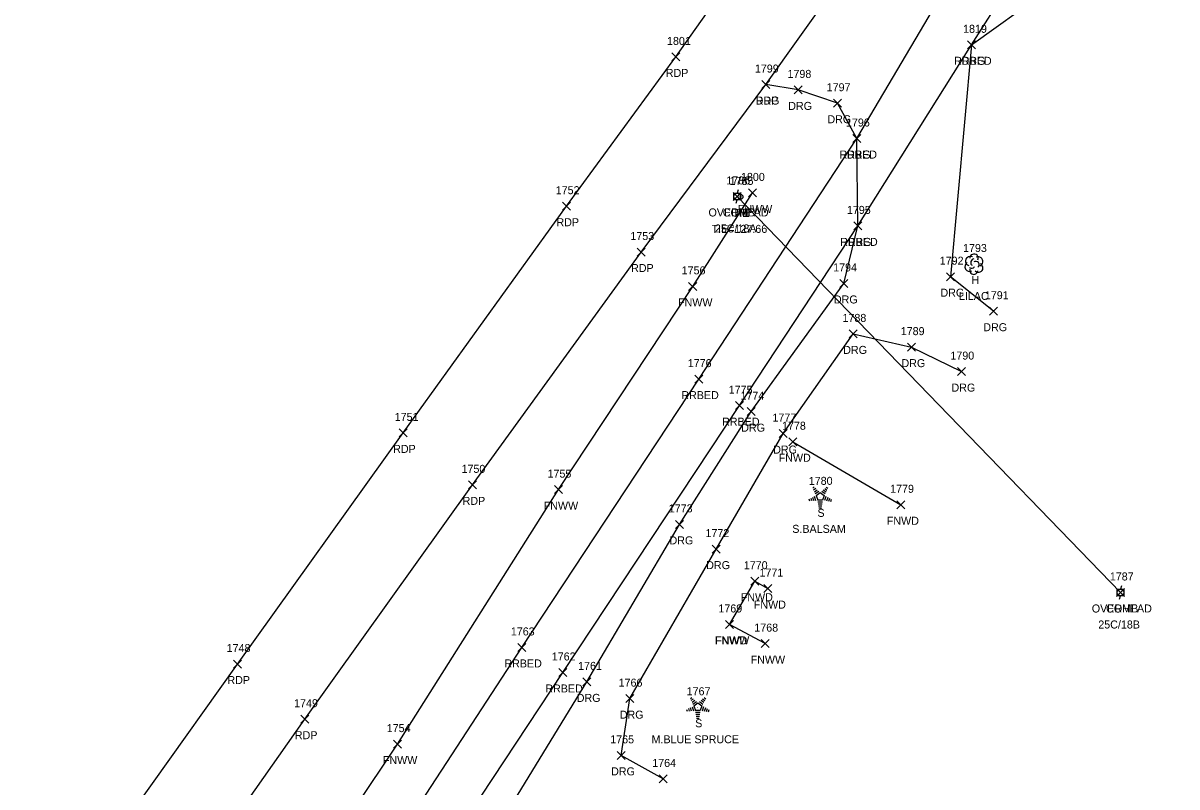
# Model space of a CAD drawing. Extents: x 1508122 to 1515053, y 865012 to 875267.
# Drawn here: x 1511441.4 to 1511729.8, y 870213.2 to 870404.1 of the extents above; entities that cross this region are included whole.
import ezdxf

# ---------------------------------------------------------------- set-up
doc = ezdxf.new("R2010")
doc.units = 0
for name, color, linetype in [('C_A', 7, 'Continuous'), ('C_C', 7, 'Continuous'), ('C_I', 7, 'Continuous'), ('CBP', 7, 'Continuous'), ('L_A', 7, 'Continuous'), ('L_C', 7, 'Continuous'), ('L_I', 7, 'Continuous'), ('L_TIC', 7, 'Continuous'), ('LFNC', 7, 'Continuous'), ('LTC', 7, 'Continuous'), ('LTD', 7, 'Continuous'), ('P_A', 7, 'Continuous'), ('P_I', 7, 'Continuous'), ('P_TIC', 7, 'Continuous'), ('PET', 7, 'Continuous'), ('R_A', 7, 'Continuous'), ('R_I', 7, 'Continuous'), ('R_TIC', 7, 'Continuous'), ('RDG', 7, 'Continuous'), ('RRB', 7, 'Continuous'), ('U_A', 7, 'Continuous'), ('U_C', 7, 'Continuous'), ('U_I', 7, 'Continuous'), ('U_TIC', 7, 'Continuous'), ('UP', 7, 'Continuous'), ('UT', 7, 'Continuous')]:
    doc.layers.add(name, color=color, linetype=linetype)

msp = doc.modelspace()

# ---------------------------------------------------------------- linework, layer by layer
at = {"layer": 'CBP'}
for radius in [0.625, 0.0833]:
    msp.add_circle((1511620.71, 870360.64), radius, dxfattribs=at)
at = {"layer": 'L_TIC'}
for points in [[(1511622.7, 870360.63), (1511624.7, 870362.63)], [(1511624.7, 870360.63), (1511622.7, 870362.63)], [(1511607.77, 870337.28), (1511609.77, 870339.28)], [(1511609.77, 870337.28), (1511607.77, 870339.28)], [(1511632.79, 870298.45), (1511634.79, 870300.45)], [(1511634.79, 870298.45), (1511632.79, 870300.45)], [(1511574.2, 870286.48), (1511576.2, 870288.48)], [(1511576.2, 870286.48), (1511574.2, 870288.48)], [(1511659.82, 870282.7), (1511661.82, 870284.7)], [(1511661.82, 870282.7), (1511659.82, 870284.7)], [(1511623.33, 870263.6), (1511625.33, 870265.6)], [(1511625.33, 870263.6), (1511623.33, 870265.6)], [(1511626.59, 870261.75), (1511628.59, 870263.75)], [(1511628.59, 870261.75), (1511626.59, 870263.75)], [(1511616.95, 870252.79), (1511618.95, 870254.79)], [(1511618.95, 870252.79), (1511616.95, 870254.79)], [(1511616.95, 870252.79), (1511618.95, 870254.79)], [(1511618.95, 870252.79), (1511616.95, 870254.79)], [(1511625.92, 870248), (1511627.92, 870250)], [(1511627.92, 870248), (1511625.92, 870250)], [(1511534.01, 870222.89), (1511536.01, 870224.89)], [(1511536.01, 870222.89), (1511534.01, 870224.89)]]:
    msp.add_lwpolyline(points, dxfattribs=at)
at = {"layer": 'LFNC'}
for points in [[(1511290.91, 869849.18), (1511327.8, 869904.4), (1511394.98, 870009.98), (1511425.13, 870055.54), (1511455.87, 870105.19), (1511491.53, 870158.85), (1511535.01, 870223.89), (1511575.2, 870287.48), (1511608.77, 870338.28), (1511623.7, 870361.63)], [(1511633.79, 870299.45), (1511660.82, 870283.7)], [(1511617.95, 870253.79), (1511624.33, 870264.6), (1511627.59, 870262.75)], [(1511626.92, 870249), (1511617.95, 870253.79)]]:
    msp.add_lwpolyline(points, dxfattribs=at)
at = {"layer": 'LTC'}
for p, q in [((1511638.77, 870287.89), (1511639.12, 870288.15)), ((1511638.98, 870287.43), (1511639.51, 870287.81)), ((1511639.19, 870286.96), (1511639.89, 870287.47)), ((1511639.4, 870286.5), (1511640.27, 870287.13)), ((1511639.62, 870286.04), (1511640.63, 870286.77)), ((1511640.63, 870286.77), (1511641.63, 870286.05)), ((1511641.05, 870287.09), (1511641.86, 870286.5)), ((1511641.42, 870287.44), (1511642.1, 870286.94)), ((1511641.79, 870287.78), (1511642.34, 870287.39)), ((1511642.17, 870288.13), (1511642.58, 870287.83)), ((1511637.8, 870285.17), (1511637.95, 870284.7)), ((1511638.26, 870285.39), (1511638.47, 870284.74)), ((1511638.71, 870285.6), (1511638.98, 870284.77)), ((1511639.17, 870285.82), (1511639.5, 870284.8)), ((1511639.62, 870286.04), (1511640.01, 870284.85)), ((1511641.24, 870284.85), (1511640.01, 870284.85)), ((1511641.2, 870284.35), (1511640.06, 870284.35)), ((1511641.12, 870283.85), (1511640.13, 870283.85)), ((1511641.63, 870286.05), (1511641.24, 870284.85)), ((1511642.07, 870285.78), (1511641.73, 870284.74)), ((1511642.51, 870285.53), (1511642.22, 870284.64)), ((1511642.96, 870285.28), (1511642.72, 870284.55)), ((1511643.4, 870285.03), (1511643.21, 870284.45)), ((1511641.03, 870283.35), (1511640.2, 870283.35)), ((1511640.95, 870282.85), (1511640.27, 870282.85)), ((1511608.21, 870235.31), (1511608.56, 870235.56)), ((1511608.42, 870234.84), (1511608.95, 870235.22)), ((1511608.63, 870234.37), (1511609.33, 870234.89)), ((1511610.86, 870234.85), (1511611.54, 870234.36)), ((1511611.23, 870235.2), (1511611.78, 870234.8)), ((1511611.61, 870235.55), (1511612.02, 870235.24)), ((1511607.24, 870232.58), (1511607.39, 870232.12)), ((1511607.7, 870232.8), (1511607.91, 870232.15)), ((1511608.15, 870233.02), (1511608.42, 870232.18)), ((1511608.61, 870233.23), (1511608.94, 870232.22)), ((1511608.84, 870233.91), (1511609.71, 870234.55)), ((1511609.06, 870233.45), (1511610.07, 870234.19)), ((1511609.06, 870233.45), (1511609.45, 870232.26)), ((1511610.68, 870232.26), (1511609.45, 870232.26)), ((1511610.07, 870234.19), (1511611.07, 870233.46)), ((1511610.49, 870234.5), (1511611.3, 870233.91)), ((1511611.07, 870233.46), (1511610.68, 870232.26)), ((1511611.51, 870233.19), (1511611.17, 870232.15)), ((1511611.95, 870232.94), (1511611.66, 870232.06)), ((1511612.4, 870232.69), (1511612.16, 870231.96)), ((1511612.84, 870232.44), (1511612.65, 870231.87)), ((1511610.64, 870231.76), (1511609.5, 870231.76)), ((1511610.56, 870231.26), (1511609.57, 870231.26)), ((1511610.47, 870230.76), (1511609.64, 870230.76)), ((1511610.39, 870230.26), (1511609.71, 870230.26))]:
    msp.add_line(p, q, dxfattribs=at)
at = {"layer": 'LTD'}
msp.add_line((1511679.03, 870343.87), (1511679.03, 870343.87), dxfattribs=at)
msp.add_line((1511679.03, 870343.87), (1511679.03, 870343.87), dxfattribs=at)
msp.add_arc((1511679.08, 870345.31), 1.05, 335.5272, 180.9563, dxfattribs=at)
for centre, major_axis, ratio, start_param, end_param in [((1511678.24, 870344.54), (1.21, -0.51), 0.895232, 1.570796, 4.712389), ((1511678.82, 870344.33), (-0.208, -0.792), 0.645439, 3.141593, 6.283185), ((1511679.53, 870343.71), (-0.5, 0.667), 0.989748, 3.141593, 6.283185), ((1511680.07, 870344.46), (-1.14, -0.48), 0.949671, 1.570796, 4.712389), ((1511677.95, 870343.17), (0.58, -1.04), 0.959034, 3.141593, 6.283185), ((1511679.03, 870342.37), (0.26, 1.06), 0.942809, 1.570796, 4.712389), ((1511678.57, 870343.12), (-0.625, -0.083), 0.423636, 0, 3.141593), ((1511680.03, 870343.04), (-1.09, 0.79), 0.841452, 1.570796, 4.712389)]:
    msp.add_ellipse(centre, major_axis=major_axis, ratio=ratio, start_param=start_param, end_param=end_param, dxfattribs=at)
at = {"layer": 'P_TIC'}
for points in [[(1511603.57, 870394.61), (1511605.57, 870396.61)], [(1511605.57, 870394.61), (1511603.57, 870396.61)], [(1511626.03, 870387.71), (1511628.03, 870389.71)], [(1511628.03, 870387.71), (1511626.03, 870389.71)], [(1511576.25, 870357.31), (1511578.25, 870359.31)], [(1511578.25, 870357.31), (1511576.25, 870359.31)], [(1511594.89, 870345.86), (1511596.89, 870347.86)], [(1511596.89, 870345.86), (1511594.89, 870347.86)], [(1511535.43, 870300.66), (1511537.43, 870302.66)], [(1511537.43, 870300.66), (1511535.43, 870302.66)], [(1511552.79, 870287.68), (1511554.79, 870289.68)], [(1511554.79, 870287.68), (1511552.79, 870289.68)], [(1511494.01, 870242.9), (1511496.01, 870244.9)], [(1511496.01, 870242.9), (1511494.01, 870244.9)], [(1511510.87, 870229.12), (1511512.87, 870231.12)], [(1511512.87, 870229.12), (1511510.87, 870231.12)]]:
    msp.add_lwpolyline(points, dxfattribs=at)
at = {"layer": 'PET'}
for points in [[(1511383.61, 870084.12), (1511412.26, 870126.56), (1511452.57, 870184.22), (1511495.01, 870243.9), (1511536.43, 870301.66), (1511577.25, 870358.31), (1511604.57, 870395.61), (1511633.77, 870437), (1511660.33, 870476.14), (1511693.36, 870526.39), (1511725.02, 870575.36), (1511757.6, 870625.52), (1511818.4, 870716.85), (1511845.17, 870758.16), (1511876.46, 870805.52)], [(1511401.8, 870072.69), (1511429.85, 870113.63), (1511470.29, 870171.01), (1511511.87, 870230.12), (1511553.79, 870288.68), (1511595.89, 870346.86), (1511627.03, 870388.71), (1511652.98, 870425.11), (1511678.36, 870464.06), (1511711.38, 870514.06), (1511744.84, 870564.55), (1511778.97, 870616.56), (1511830.16, 870695.92), (1511863.87, 870746.26), (1511895.07, 870793.96)]]:
    msp.add_lwpolyline(points, dxfattribs=at)
at = {"layer": 'R_TIC'}
for points in [[(1511677.48, 870397.64), (1511679.48, 870399.64)], [(1511679.48, 870397.64), (1511677.48, 870399.64)], [(1511677.48, 870397.64), (1511679.48, 870399.64)], [(1511679.48, 870397.64), (1511677.48, 870399.64)], [(1511626.03, 870387.71), (1511628.03, 870389.71)], [(1511628.03, 870387.71), (1511626.03, 870389.71)], [(1511634.16, 870386.37), (1511636.16, 870388.37)], [(1511636.16, 870386.37), (1511634.16, 870388.37)], [(1511643.95, 870383.04), (1511645.95, 870385.04)], [(1511645.95, 870383.04), (1511643.95, 870385.04)], [(1511648.82, 870374.22), (1511650.82, 870376.22)], [(1511650.82, 870374.22), (1511648.82, 870376.22)], [(1511648.82, 870374.22), (1511650.82, 870376.22)], [(1511650.82, 870374.22), (1511648.82, 870376.22)], [(1511649.01, 870352.39), (1511651.01, 870354.39)], [(1511651.01, 870352.39), (1511649.01, 870354.39)], [(1511649.01, 870352.39), (1511651.01, 870354.39)], [(1511651.01, 870352.39), (1511649.01, 870354.39)], [(1511672.21, 870339.7), (1511674.21, 870341.7)], [(1511674.21, 870339.7), (1511672.21, 870341.7)], [(1511645.57, 870338.01), (1511647.57, 870340.01)], [(1511647.57, 870338.01), (1511645.57, 870340.01)], [(1511682.91, 870331.07), (1511684.91, 870333.07)], [(1511684.91, 870331.07), (1511682.91, 870333.07)], [(1511647.91, 870325.4), (1511649.91, 870327.4)], [(1511649.91, 870325.4), (1511647.91, 870327.4)], [(1511662.47, 870322.09), (1511664.47, 870324.09)], [(1511664.47, 870322.09), (1511662.47, 870324.09)], [(1511609.28, 870314.1), (1511611.28, 870316.1)], [(1511611.28, 870314.1), (1511609.28, 870316.1)], [(1511674.96, 870315.98), (1511676.96, 870317.98)], [(1511676.96, 870315.98), (1511674.96, 870317.98)], [(1511619.47, 870307.47), (1511621.47, 870309.47)], [(1511621.47, 870307.47), (1511619.47, 870309.47)], [(1511622.41, 870305.97), (1511624.41, 870307.97)], [(1511624.41, 870305.97), (1511622.41, 870307.97)], [(1511630.4, 870300.49), (1511632.4, 870302.49)], [(1511632.4, 870300.49), (1511630.4, 870302.49)], [(1511604.49, 870277.8), (1511606.49, 870279.8)], [(1511606.49, 870277.8), (1511604.49, 870279.8)], [(1511613.66, 870271.62), (1511615.66, 870273.62)], [(1511615.66, 870271.62), (1511613.66, 870273.62)], [(1511565.07, 870247.05), (1511567.07, 870249.05)], [(1511567.07, 870247.05), (1511565.07, 870249.05)], [(1511575.3, 870240.79), (1511577.3, 870242.79)], [(1511577.3, 870240.79), (1511575.3, 870242.79)], [(1511581.31, 870238.44), (1511583.31, 870240.44)], [(1511583.31, 870238.44), (1511581.31, 870240.44)], [(1511592.06, 870234.25), (1511594.06, 870236.25)], [(1511594.06, 870234.25), (1511592.06, 870236.25)], [(1511589.91, 870220.08), (1511591.91, 870222.08)], [(1511591.91, 870220.08), (1511589.91, 870222.08)], [(1511600.41, 870214.18), (1511602.41, 870216.18)], [(1511602.41, 870214.18), (1511600.41, 870216.18)]]:
    msp.add_lwpolyline(points, dxfattribs=at)
at = {"layer": 'RDG'}
for points in [[(1511678.48, 870398.64), (1511696.33, 870411.58), (1511712.66, 870429.06), (1511744.16, 870465.13), (1511764.81, 870482.14), (1511795.62, 870494.83)], [(1511678.48, 870398.64), (1511673.21, 870340.7)], [(1511593.38, 870196.12), (1511577.29, 870201.4), (1511561.28, 870182.52), (1511551.38, 870188.88), (1511582.31, 870239.44), (1511605.49, 870278.8), (1511623.41, 870306.97), (1511646.57, 870339.01), (1511650.01, 870353.39), (1511649.82, 870375.22), (1511644.95, 870384.04), (1511635.16, 870387.37), (1511627.03, 870388.71)], [(1511683.91, 870332.07), (1511673.21, 870340.7)], [(1511601.41, 870215.18), (1511590.91, 870221.08), (1511593.06, 870235.25), (1511614.66, 870272.62), (1511631.4, 870301.49), (1511648.91, 870326.4), (1511663.47, 870323.09), (1511675.96, 870316.98)]]:
    msp.add_lwpolyline(points, dxfattribs=at)
at = {"layer": 'RRB'}
for points in [[(1511436.1, 870048.65), (1511490.68, 870132.35), (1511525.95, 870186.51), (1511566.07, 870248.05), (1511610.28, 870315.1), (1511649.82, 870375.22), (1511670.06, 870409.5), (1511721.74, 870485.89), (1511765, 870552.19), (1511815.5, 870626.59), (1511852.37, 870681.17), (1511885.93, 870729.88), (1511937.25, 870806.65), (1511989.72, 870883.94), (1512013.79, 870920.57), (1512083.27, 871021.96), (1512129.35, 871090.14), (1512163.74, 871140.81), (1512188.75, 871177.43), (1512243.74, 871258.31), (1512286.31, 871321.24), (1512333.89, 871390.89), (1512361.47, 871430.92), (1512395.79, 871481.56)], [(1511445.67, 870042.93), (1511499.01, 870126.5), (1511535.52, 870180.01), (1511576.3, 870241.79), (1511620.47, 870308.47), (1511650.01, 870353.39), (1511678.48, 870398.64), (1511696.26, 870426.71), (1511730.11, 870478.59), (1511774.8, 870546.45), (1511824.54, 870619.21), (1511862.36, 870674.46), (1511895.49, 870722.79), (1511947.32, 870799.15)]]:
    msp.add_lwpolyline(points, dxfattribs=at)
at = {"layer": 'U_TIC'}
for points in [[(1511618.92, 870359.75), (1511620.92, 870361.75)], [(1511620.92, 870359.75), (1511618.92, 870361.75)], [(1511714.71, 870260.78), (1511716.71, 870262.78)], [(1511716.71, 870260.78), (1511714.71, 870262.78)]]:
    msp.add_lwpolyline(points, dxfattribs=at)
at = {"layer": 'UP'}
for p, q in [((1511620.17, 870362.41), (1511619.92, 870361.58)), ((1511619.08, 870359.91), (1511619.08, 870361.58)), ((1511619.08, 870361.58), (1511620.75, 870361.58)), ((1511620.75, 870359.91), (1511619.08, 870359.91)), ((1511619.67, 870359.08), (1511619.92, 870359.91)), ((1511619.92, 870360.75), (1511619.92, 870360.75)), ((1511620.75, 870361.58), (1511620.75, 870359.91)), ((1511714.88, 870260.95), (1511714.88, 870262.61)), ((1511714.88, 870262.61), (1511716.54, 870262.61)), ((1511716.54, 870260.95), (1511714.88, 870260.95)), ((1511715.46, 870260.11), (1511715.71, 870260.95)), ((1511715.96, 870263.45), (1511715.71, 870262.61)), ((1511715.71, 870261.78), (1511715.71, 870261.78)), ((1511716.54, 870262.61), (1511716.54, 870260.95))]:
    msp.add_line(p, q, dxfattribs=at)
for centre in [(1511619.92, 870360.75), (1511715.71, 870261.78)]:
    msp.add_circle(centre, 0.833, dxfattribs=at)
at = {"layer": 'UT'}
msp.add_lwpolyline([(1511619.92, 870360.75), (1511715.71, 870261.78)], dxfattribs=at)

# ---------------------------------------------------------------- texts
at = {"layer": 'C_A'}
msp.add_text('TIE', height=2, dxfattribs=at).set_placement((1511618.78, 870355.64))
at = {"layer": 'C_C'}
msp.add_text('TIE=127.66', height=2, dxfattribs=at).set_placement((1511613.5, 870351.64))
at = {"layer": 'C_I'}
msp.add_text('1785', height=2, dxfattribs=at).set_placement((1511618.01, 870363.64))
at = {"layer": 'L_A'}
for s, p in [('FNWW', (1511620.05, 870356.63)), ('H', (1511678.46, 870338.87)), ('FNWW', (1511605.11, 870333.28)), ('FNWD', (1511630.26, 870294.45)), ('FNWW', (1511571.54, 870282.48)), ('S', (1511639.96, 870280.68)), ('FNWD', (1511657.29, 870278.7)), ('FNWD', (1511620.79, 870259.6)), ('FNWD', (1511624.06, 870257.75)), ('FNWW', (1511614.29, 870248.79)), ('FNWD', (1511614.41, 870248.79)), ('FNWW', (1511623.26, 870244)), ('S', (1511609.4, 870228.1)), ('FNWW', (1511531.35, 870218.89))]:
    msp.add_text(s, height=2, dxfattribs=at).set_placement(p)
at = {"layer": 'L_C'}
for s, p in [('LILAC', (1511675.31, 870334.87)), ('S.BALSAM', (1511633.66, 870276.68)), ('M.BLUE SPRUCE', (1511598.5, 870224.1))]:
    msp.add_text(s, height=2, dxfattribs=at).set_placement(p)
at = {"layer": 'L_I'}
for s, p in [('1800', (1511620.84, 870364.63)), ('1793', (1511676.34, 870346.87)), ('1756', (1511606.02, 870341.28)), ('1778', (1511631.1, 870302.45)), ('1755', (1511572.5, 870290.48)), ('1780', (1511637.79, 870288.68)), ('1779', (1511658.12, 870286.7)), ('1770', (1511621.55, 870267.6)), ('1771', (1511625.47, 870265.75)), ('1769', (1511615.2, 870256.79)), ('1769', (1511615.2, 870256.79)), ('1768', (1511624.18, 870252)), ('1767', (1511607.27, 870236.1)), ('1754', (1511532.31, 870226.89))]:
    msp.add_text(s, height=2, dxfattribs=at).set_placement(p)
at = {"layer": 'LTC'}
for p in [(1511640.51, 870285.79), (1511609.95, 870233.2)]:
    msp.add_text('.', height=1.04, rotation=270, dxfattribs=at).set_placement(p)
at = {"layer": 'P_A'}
for p in [(1511602.05, 870390.61), (1511624.51, 870383.71), (1511574.73, 870353.31), (1511593.38, 870341.86), (1511533.92, 870296.66), (1511551.28, 870283.68), (1511492.5, 870238.9), (1511509.36, 870225.12)]:
    msp.add_text('RDP', height=2, dxfattribs=at).set_placement(p)
at = {"layer": 'P_I'}
for s, p in [('1801', (1511602.36, 870398.61)), ('1799', (1511624.32, 870391.71)), ('1752', (1511574.55, 870361.31)), ('1753', (1511593.2, 870349.86)), ('1751', (1511534.31, 870304.66)), ('1750', (1511551.01, 870291.68)), ('1748', (1511492.31, 870246.9)), ('1749', (1511509.17, 870233.12))]:
    msp.add_text(s, height=2, dxfattribs=at).set_placement(p)
at = {"layer": 'R_A'}
for s, p in [('RRBED', (1511674.13, 870393.64)), ('DRG', (1511675.97, 870393.64)), ('DRG', (1511624.51, 870383.71)), ('DRG', (1511632.65, 870382.37)), ('DRG', (1511642.44, 870379.04)), ('RRBED', (1511645.47, 870370.22)), ('DRG', (1511647.31, 870370.22)), ('RRBED', (1511645.65, 870348.39)), ('DRG', (1511647.5, 870348.39)), ('DRG', (1511644.06, 870334.01)), ('DRG', (1511670.69, 870335.7)), ('DRG', (1511681.4, 870327.07)), ('DRG', (1511646.39, 870321.4)), ('DRG', (1511660.95, 870318.09)), ('DRG', (1511673.45, 870311.98)), ('RRBED', (1511605.93, 870310.1)), ('RRBED', (1511616.12, 870303.47)), ('DRG', (1511620.9, 870301.97)), ('DRG', (1511628.89, 870296.49)), ('DRG', (1511602.98, 870273.8)), ('DRG', (1511612.15, 870267.62)), ('RRBED', (1511561.71, 870243.05)), ('RRBED', (1511571.94, 870236.79)), ('DRG', (1511579.8, 870234.44)), ('DRG', (1511590.55, 870230.25)), ('DRG', (1511588.39, 870216.08))]:
    msp.add_text(s, height=2, dxfattribs=at).set_placement(p)
at = {"layer": 'R_I'}
for s, p in [('1819', (1511676.35, 870401.64)), ('1819', (1511676.35, 870401.64)), ('1799', (1511624.32, 870391.71)), ('1798', (1511632.47, 870390.37)), ('1797', (1511642.26, 870387.04)), ('1796', (1511647.08, 870378.22)), ('1796', (1511647.08, 870378.22)), ('1795', (1511647.32, 870356.39)), ('1795', (1511647.32, 870356.39)), ('1792', (1511670.51, 870343.7)), ('1794', (1511643.88, 870342.01)), ('1791', (1511681.79, 870335.07)), ('1788', (1511646.21, 870329.4)), ('1789', (1511660.77, 870326.09)), ('1790', (1511673.18, 870319.98)), ('1776', (1511607.54, 870318.1)), ('1775', (1511617.78, 870311.47)), ('1774', (1511620.72, 870309.97)), ('1777', (1511628.71, 870304.49)), ('1773', (1511602.8, 870281.8)), ('1772', (1511611.97, 870275.62)), ('1763', (1511563.33, 870251.05)), ('1762', (1511573.56, 870244.79)), ('1761', (1511580.14, 870242.44)), ('1766', (1511590.27, 870238.25)), ('1765', (1511588.17, 870224.08)), ('1764', (1511598.67, 870218.18))]:
    msp.add_text(s, height=2, dxfattribs=at).set_placement(p)
at = {"layer": 'U_A'}
for s, p in [('OVERHEAD', (1511612.73, 870355.75)), ('COMB', (1511616.3, 870355.75)), ('OVERHEAD', (1511708.52, 870256.78)), ('COMB', (1511712.1, 870256.78))]:
    msp.add_text(s, height=2, dxfattribs=at).set_placement(p)
at = {"layer": 'U_C'}
for s, p in [('25C/18A', (1511614.32, 870351.75)), ('25C/18B', (1511710.14, 870252.78))]:
    msp.add_text(s, height=2, dxfattribs=at).set_placement(p)
at = {"layer": 'U_I'}
for s, p in [('1786', (1511617.17, 870363.75)), ('1786', (1511617.17, 870363.75)), ('1787', (1511713.02, 870264.78)), ('1787', (1511713.02, 870264.78))]:
    msp.add_text(s, height=2, dxfattribs=at).set_placement(p)

doc.saveas('drawing.dxf')
